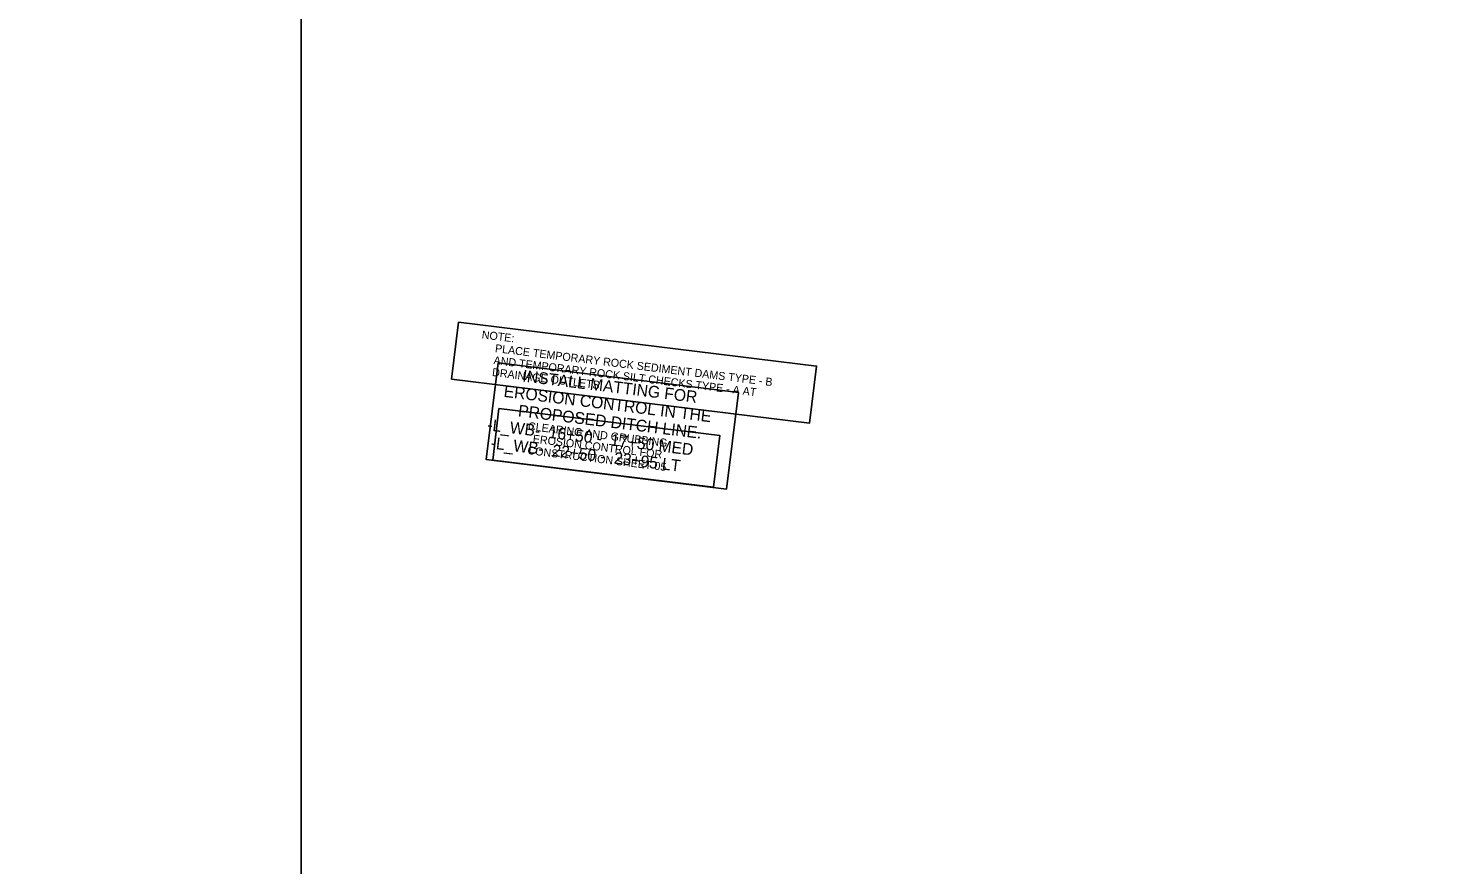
# Model space of a CAD drawing. Extents: x 2470000 to 2520000, y 340000 to 380000.
# Drawn here: x 2479795 to 2480859, y 366476 to 367103 of the extents above; entities that cross this region are included whole.
import ezdxf

# ---------------------------------------------------------------- set-up
doc = ezdxf.new("R2010")
doc.units = 0
for name, color, linetype in [('Construction Sheet Number Note CG CELL', 7, 'Continuous'), ('Matting in Proposed Ditchline Note Final CELL', 7, 'Continuous'), ('Scratch_Level_6', 7, 'Continuous'), ('Sediment Dams and Silt Check Note CG CELL', 7, 'Continuous')]:
    doc.layers.add(name, color=color, linetype=linetype)

# ---------------------------------------------------------------- blocks, each defined once
blk = doc.blocks.new('CGNT2')
at = {"layer": 'Sediment Dams and Silt Check Note CG CELL'}
blk.add_lwpolyline([(-2.704, 0.431), (2.704, 0.43125), (2.704, -0.43), (-2.704, -0.43)], close=True, dxfattribs=at)
for s, p in [('NOTE:', (-2.335, 0.231)), ('     PLACE TEMPORARY ROCK SEDIMENT DAMS TYPE - B', (-2.335, 0.05125)), ('     AND TEMPORARY ROCK SILT CHECKS TYPE - A AT', (-2.335, -0.129)), ('     DRAINAGE OUTLETS.', (-2.335, -0.309))]:
    blk.add_text(s, height=0.12, dxfattribs=at).set_placement(p)

msp = doc.modelspace()

# ---------------------------------------------------------------- linework, layer by layer
at = {"layer": 'Construction Sheet Number Note CG CELL'}
msp.add_lwpolyline([(2480148.3, 366817.7), (2480314, 366797.4), (2480309.2, 366758.7), (2480143.6, 366779)], close=True, dxfattribs=at)
at = {"layer": 'Matting in Proposed Ditchline Note Final CELL'}
msp.add_lwpolyline([(2480147.7, 366851.9), (2480327.8, 366829.8), (2480318.9, 366757.4), (2480138.8, 366779.5)], close=True, dxfattribs=at)
at = {"layer": 'Scratch_Level_6'}
for points in [[(2470000, 360000), (2480000, 360000), (2480000, 370000), (2470000, 370000)], [(2480000, 360000), (2490000, 360000), (2490000, 370000), (2480000, 370000)]]:
    msp.add_lwpolyline(points, close=True, dxfattribs=at)

# ---------------------------------------------------------------- block references
at = {"layer": 'Sediment Dams and Silt Check Note CG CELL', "xscale": 50.00000000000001, "yscale": 50.00000000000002, "rotation": -6.9977038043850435}
msp.add_blockref('CGNT2', (2480249.6, 366844.6), dxfattribs=at)

# ---------------------------------------------------------------- texts
at = {"layer": 'Construction Sheet Number Note CG CELL'}
for s, p in [('CLEARING AND GRUBBING', (2480169.8, 366801.7)), ('EROSION CONTROL FOR', (2480173.4, 366792.2)), ('CONSTRUCTION SHEET 05', (2480169.4, 366783.6))]:
    msp.add_text(s, height=6, rotation=353.0023, dxfattribs=at).set_placement(p)
at = {"layer": 'Matting in Proposed Ditchline Note Final CELL'}
for s, p in [('INSTALL MATTING FOR ', (2480165.6, 366838)), ('EROSION CONTROL IN THE', (2480151.5, 366826.5)), ('PROPOSED DITCH LINE.', (2480162.3, 366811.9)), ('-L_WB-  16+50 -  17+50 MED', (2480139.2, 366801.4)), ('-L_WB-  22+50 -  23+95 LT', (2480141.8, 366787.8))]:
    msp.add_text(s, height=8.785, rotation=353.0023, dxfattribs=at).set_placement(p)

doc.saveas('drawing.dxf')
